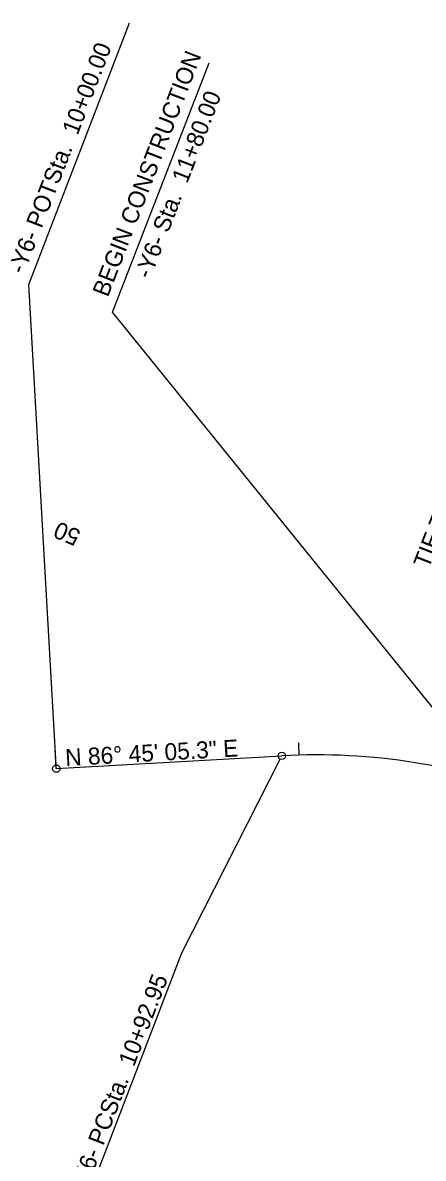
# Model space of a CAD drawing. Extents: x 1974386 to 1979988, y 776712 to 784860.
# Drawn here: x 1977437.4 to 1977602.1, y 781691.1 to 782158.5 of the extents above; entities that cross this region are included whole.
import ezdxf

# ---------------------------------------------------------------- set-up
doc = ezdxf.new("R2010")
doc.units = 0
for name, color, linetype in [('Prop Conc 2ft 6in Curb and Gutter', 7, 'Continuous'), ('Prop Conc 4in Sidewalk', 7, 'Continuous'), ('Prop Conc 5in Monolithic Keyed In Island', 7, 'Continuous'), ('Prop Dimension Text', 7, 'Continuous'), ('Prop EOT', 7, 'Continuous'), ('Prop Horizontal Alignment', 7, 'Continuous'), ('Prop Horizontal Alignment Direction Label', 7, 'Continuous'), ('Prop Horizontal Alignment Station Label', 7, 'Continuous'), ('Prop Horizontal Alignment Tick Label', 7, 'Continuous'), ('Prop Horizontal Alignment Tick Large', 7, 'Continuous'), ('Prop Horizontal Alignment Tick Small', 7, 'Continuous'), ('Prop Lane Lines', 7, 'Continuous')]:
    doc.layers.add(name, color=color, linetype=linetype)

msp = doc.modelspace()

# ---------------------------------------------------------------- linework, layer by layer
at = {"layer": 'Prop Conc 2ft 6in Curb and Gutter'}
msp.add_arc((1981585.24, 780180.82), 4226.75, 157.96844, 161.65559, dxfattribs=at)
at = {"layer": 'Prop Conc 4in Sidewalk'}
for radius, start in [(4236.25, 157.96844), (4231.25, 157.97234)]:
    msp.add_arc((1981585.24, 780180.82), radius, start, 162.22085, dxfattribs=at)
at = {"layer": 'Prop Conc 5in Monolithic Keyed In Island'}
msp.add_arc((1981585.24, 780180.82), 4208, 157.44193, 162.14647, dxfattribs=at)
at = {"layer": 'Prop EOT'}
for radius, start, end in [(4208.75, 157.44193, 162.22085), (4224.75, 157.96844, 161.65559)]:
    msp.add_arc((1981585.24, 780180.82), radius, start, end, dxfattribs=at)
at = {"layer": 'Prop Horizontal Alignment'}
msp.add_line((1977451.18, 781851.49), (1977543.98, 781856.76), dxfattribs=at)
for centre, radius, start, end in [((1981585.24, 780180.82), 4200, 153.11985, 162.22085), ((1977558.41, 781602.52), 254.65, 68.5255, 93.2485)]:
    msp.add_arc(centre, radius, start, end, dxfattribs=at)
at = {"layer": 'Prop Horizontal Alignment Station Label'}
for p, q in [((1977439.87, 782050.72), (1977481.22, 782158.54)), ((1977474.28, 782039.42), (1977514, 782141.99)), ((1977451.1, 781852.99), (1977439.87, 782050.72)), ((1977630.04, 781846.89), (1977474.28, 782039.42)), ((1977502.75, 781775.73), (1977543.3, 781855.42)), ((1977461.4, 781667.9), (1977502.75, 781775.73))]:
    msp.add_line(p, q, dxfattribs=at)
for centre in [(1977543.98, 781856.76), (1977451.18, 781851.49)]:
    msp.add_circle(centre, 1.5, dxfattribs=at)
at = {"layer": 'Prop Horizontal Alignment Tick Large'}
msp.add_line((1977451.18, 781851.49), (1977450.73, 781859.48), dxfattribs=at)
at = {"layer": 'Prop Horizontal Alignment Tick Small'}
msp.add_line((1977551.03, 781857.06), (1977550.88, 781862.06), dxfattribs=at)
at = {"layer": 'Prop Lane Lines'}
msp.add_arc((1981585.24, 780180.82), 4191.25, 158.03179, 162.22085, dxfattribs=at)

# ---------------------------------------------------------------- texts
at = {"layer": 'Prop Dimension Text'}
msp.add_text('TIE TO EXIST.  48" SIDEWALK', height=7, rotation=68.7131, dxfattribs=at).set_placement((1977604.41, 781933.52))
at = {"layer": 'Prop Horizontal Alignment Direction Label'}
msp.add_text('N 86%%d 45\' 05.3" E', height=7, rotation=3.2485, dxfattribs=at).set_placement((1977455.03, 781852.52))
at = {"layer": 'Prop Horizontal Alignment Station Label'}
for s, p in [('-Y6- POTSta.  10+00.00', (1977437.79, 782054.67)), ('BEGIN CONSTRUCTION', (1977472.38, 782045.25)), ('-Y6- Sta.  11+80.00', (1977489.83, 782052.74)), ('-Y6- PCSta.  10+92.95', (1977463.22, 781677.06))]:
    msp.add_text(s, height=7, rotation=68.8775, dxfattribs=at).set_placement(p)
at = {"layer": 'Prop Horizontal Alignment Tick Label'}
msp.add_text('50', height=7, rotation=156.826, dxfattribs=at).set_placement((1977461.7, 781949.35))

doc.saveas('drawing.dxf')
